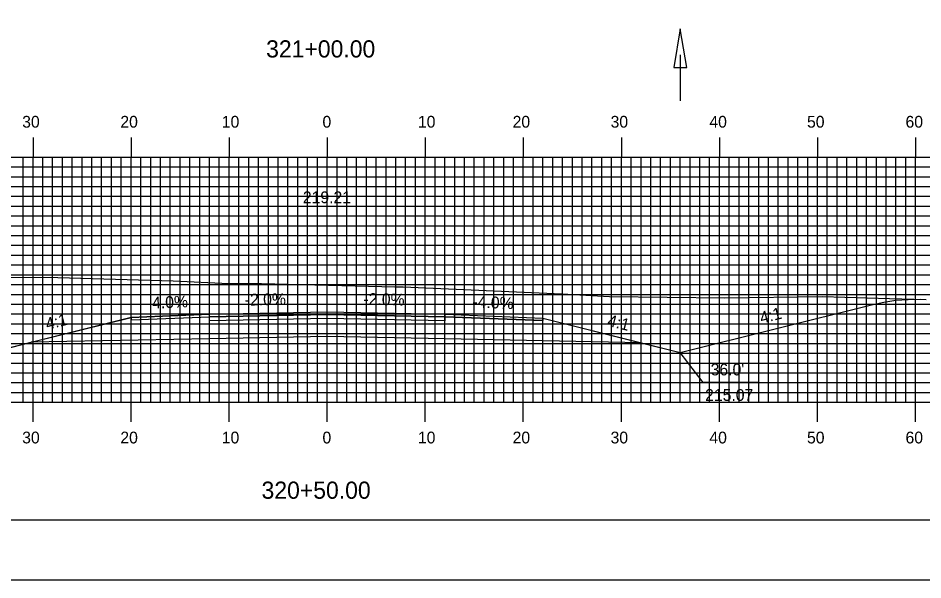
# Model space of a CAD drawing. Extents: x 1820424 to 1820768, y 442591 to 442811.
# Drawn here: x 1820558.7 to 1820650.9, y 442590.5 to 442647.8 of the extents above; entities that cross this region are included whole.
import ezdxf

# ---------------------------------------------------------------- set-up
doc = ezdxf.new("R2010")
doc.units = 0
for name, color, linetype in [('ANNOTATION', 7, 'Continuous'), ('BORDER', 7, 'Continuous'), ('D_Drainage_Ditch_Line', 7, 'Continuous'), ('D_Roadway_Centerline', 7, 'Continuous'), ('D_Roadway_Centerline_Text', 7, 'Continuous'), ('D_Roadway_Edge_Shoulder', 7, 'Continuous'), ('D_Roadway_Edge_TW', 7, 'Continuous'), ('D_Roadway_Pavement', 7, 'Continuous'), ('D_Roadway_SlopeLines', 7, 'Continuous'), ('D_Roadway_SubGrade', 7, 'Continuous'), ('H_V ANNOTATION', 7, 'Continuous'), ('MAJOR', 7, 'Continuous'), ('MINOR', 7, 'Continuous'), ('PLOT BOUNDARY', 7, 'Continuous'), ('S_Roadway_Centerline', 7, 'Continuous')]:
    doc.layers.add(name, color=color, linetype=linetype)

msp = doc.modelspace()

# ---------------------------------------------------------------- linework, layer by layer
at = {"layer": 'ANNOTATION'}
msp.add_lwpolyline([(1820634.22, 442610.677), (1820628.528, 442610.677), (1820626.204, 442613.737)], dxfattribs=at)
at = {"layer": 'BORDER'}
msp.add_lwpolyline([(1820440.604, 442596.665), (1820760.604, 442596.665), (1820760.604, 442806.665), (1820440.604, 442806.665)], close=True, dxfattribs=at)
at = {"layer": 'D_Drainage_Ditch_Line'}
msp.add_line((1820626.204, 442644.105), (1820626.204, 442639.406), dxfattribs=at)
msp.add_lwpolyline([(1820625.548, 442642.793), (1820626.86, 442642.793), (1820626.204, 442646.73)], close=True, dxfattribs=at)
at = {"layer": 'D_Roadway_Centerline'}
msp.add_lwpolyline([(1820520.686, 442622.127), (1820521.936, 442622.025), (1820523.186, 442621.863), (1820524.436, 442621.641), (1820525.686, 442621.359), (1820556.03, 442613.773), (1820560.03, 442614.773), (1820570.204, 442617.317), (1820578.204, 442617.637), (1820590.204, 442617.877), (1820602.204, 442617.637), (1820612.204, 442617.237), (1820622.204, 442614.737), (1820626.204, 442613.737), (1820645.702, 442618.611), (1820646.952, 442618.88), (1820648.202, 442619.061), (1820649.452, 442619.155), (1820650.702, 442619.161)], dxfattribs=at)
at = {"layer": 'D_Roadway_Edge_Shoulder'}
for points in [[(1820578.204, 442617.637), (1820570.204, 442617.317), (1820570.204, 442617.067), (1820578.204, 442617.387)], [(1820602.204, 442617.637), (1820612.204, 442617.237), (1820612.204, 442616.987), (1820602.204, 442617.387)]]:
    msp.add_lwpolyline(points, close=True, dxfattribs=at)
at = {"layer": 'D_Roadway_Edge_TW'}
msp.add_lwpolyline([(1820578.204, 442617.387), (1820578.204, 442617.637), (1820590.204, 442617.877), (1820602.204, 442617.637), (1820602.204, 442617.387), (1820590.204, 442617.627)], close=True, dxfattribs=at)
at = {"layer": 'D_Roadway_Pavement'}
msp.add_lwpolyline([(1820578.204, 442616.97), (1820578.204, 442617.387), (1820590.204, 442617.627), (1820602.204, 442617.387), (1820602.204, 442616.97), (1820590.204, 442617.21)], close=True, dxfattribs=at)
at = {"layer": 'D_Roadway_SlopeLines'}
for points in [[(1820626.204, 442613.737), (1820645.702, 442618.611), (1820646.952, 442618.88), (1820648.202, 442619.061), (1820649.452, 442619.155), (1820650.702, 442619.161)], [(1820570.204, 442617.317), (1820556.03, 442613.773)], [(1820612.204, 442617.237), (1820626.204, 442613.737)]]:
    msp.add_lwpolyline(points, dxfattribs=at)
at = {"layer": 'D_Roadway_SubGrade'}
msp.add_lwpolyline([(1820578.204, 442615.137), (1820560.03, 442614.773), (1820570.204, 442617.317), (1820570.204, 442617.067), (1820578.204, 442617.387), (1820590.204, 442617.627), (1820602.204, 442617.387), (1820612.204, 442616.987), (1820612.204, 442617.237), (1820622.204, 442614.737), (1820602.204, 442615.137), (1820590.204, 442615.377)], close=True, dxfattribs=at)
at = {"layer": 'MAJOR'}
for p, q in [((1820560.204, 442635.669), (1820560.204, 442633.665)), ((1820570.204, 442635.669), (1820570.204, 442633.665)), ((1820580.204, 442635.669), (1820580.204, 442633.665)), ((1820590.204, 442635.669), (1820590.204, 442633.665)), ((1820600.204, 442635.669), (1820600.204, 442633.665)), ((1820610.204, 442635.669), (1820610.204, 442633.665)), ((1820620.204, 442635.669), (1820620.204, 442633.665)), ((1820630.204, 442635.669), (1820630.204, 442633.665)), ((1820640.204, 442635.669), (1820640.204, 442633.665)), ((1820650.204, 442635.669), (1820650.204, 442633.665)), ((1820450.204, 442633.665), (1820730.204, 442633.665)), ((1820450.204, 442633.665), (1820730.204, 442633.665)), ((1820560.204, 442608.665), (1820560.204, 442633.665)), ((1820570.204, 442608.665), (1820570.204, 442633.665)), ((1820580.204, 442608.665), (1820580.204, 442633.665)), ((1820590.204, 442608.665), (1820590.204, 442633.665)), ((1820600.204, 442608.665), (1820600.204, 442633.665)), ((1820610.204, 442608.665), (1820610.204, 442633.665)), ((1820620.204, 442608.665), (1820620.204, 442633.665)), ((1820630.204, 442608.665), (1820630.204, 442633.665)), ((1820640.204, 442608.665), (1820640.204, 442633.665)), ((1820650.204, 442608.665), (1820650.204, 442633.665)), ((1820450.204, 442628.665), (1820730.204, 442628.665)), ((1820450.204, 442623.665), (1820730.204, 442623.665)), ((1820450.204, 442618.665), (1820730.204, 442618.665)), ((1820450.204, 442613.665), (1820730.204, 442613.665)), ((1820450.204, 442608.665), (1820730.204, 442608.665)), ((1820450.204, 442608.665), (1820730.204, 442608.665)), ((1820560.204, 442606.661), (1820560.204, 442608.665)), ((1820570.204, 442606.661), (1820570.204, 442608.665)), ((1820580.204, 442606.661), (1820580.204, 442608.665)), ((1820590.204, 442606.661), (1820590.204, 442608.665)), ((1820600.204, 442606.661), (1820600.204, 442608.665)), ((1820610.204, 442606.661), (1820610.204, 442608.665)), ((1820620.204, 442606.661), (1820620.204, 442608.665)), ((1820630.204, 442606.661), (1820630.204, 442608.665)), ((1820640.204, 442606.661), (1820640.204, 442608.665)), ((1820650.204, 442606.661), (1820650.204, 442608.665))]:
    msp.add_line(p, q, dxfattribs=at)
at = {"layer": 'MINOR'}
for p, q in [((1820559.204, 442608.665), (1820559.204, 442633.665)), ((1820561.204, 442608.665), (1820561.204, 442633.665)), ((1820562.204, 442608.665), (1820562.204, 442633.665)), ((1820563.204, 442608.665), (1820563.204, 442633.665)), ((1820564.204, 442608.665), (1820564.204, 442633.665)), ((1820565.204, 442608.665), (1820565.204, 442633.665)), ((1820566.204, 442608.665), (1820566.204, 442633.665)), ((1820567.204, 442608.665), (1820567.204, 442633.665)), ((1820568.204, 442608.665), (1820568.204, 442633.665)), ((1820569.204, 442608.665), (1820569.204, 442633.665)), ((1820571.204, 442608.665), (1820571.204, 442633.665)), ((1820572.204, 442608.665), (1820572.204, 442633.665)), ((1820573.204, 442608.665), (1820573.204, 442633.665)), ((1820574.204, 442608.665), (1820574.204, 442633.665)), ((1820575.204, 442608.665), (1820575.204, 442633.665)), ((1820576.204, 442608.665), (1820576.204, 442633.665)), ((1820577.204, 442608.665), (1820577.204, 442633.665)), ((1820578.204, 442608.665), (1820578.204, 442633.665)), ((1820579.204, 442608.665), (1820579.204, 442633.665)), ((1820581.204, 442608.665), (1820581.204, 442633.665)), ((1820582.204, 442608.665), (1820582.204, 442633.665)), ((1820583.204, 442608.665), (1820583.204, 442633.665)), ((1820584.204, 442608.665), (1820584.204, 442633.665)), ((1820585.204, 442608.665), (1820585.204, 442633.665)), ((1820586.204, 442608.665), (1820586.204, 442633.665)), ((1820587.204, 442608.665), (1820587.204, 442633.665)), ((1820588.204, 442608.665), (1820588.204, 442633.665)), ((1820589.204, 442608.665), (1820589.204, 442633.665)), ((1820591.204, 442608.665), (1820591.204, 442633.665)), ((1820592.204, 442608.665), (1820592.204, 442633.665)), ((1820593.204, 442608.665), (1820593.204, 442633.665)), ((1820594.204, 442608.665), (1820594.204, 442633.665)), ((1820595.204, 442608.665), (1820595.204, 442633.665)), ((1820596.204, 442608.665), (1820596.204, 442633.665)), ((1820597.204, 442608.665), (1820597.204, 442633.665)), ((1820598.204, 442608.665), (1820598.204, 442633.665)), ((1820599.204, 442608.665), (1820599.204, 442633.665)), ((1820601.204, 442608.665), (1820601.204, 442633.665)), ((1820602.204, 442608.665), (1820602.204, 442633.665)), ((1820603.204, 442608.665), (1820603.204, 442633.665)), ((1820604.204, 442608.665), (1820604.204, 442633.665)), ((1820605.204, 442608.665), (1820605.204, 442633.665)), ((1820606.204, 442608.665), (1820606.204, 442633.665)), ((1820607.204, 442608.665), (1820607.204, 442633.665)), ((1820608.204, 442608.665), (1820608.204, 442633.665)), ((1820609.204, 442608.665), (1820609.204, 442633.665)), ((1820611.204, 442608.665), (1820611.204, 442633.665)), ((1820612.204, 442608.665), (1820612.204, 442633.665)), ((1820613.204, 442608.665), (1820613.204, 442633.665)), ((1820614.204, 442608.665), (1820614.204, 442633.665)), ((1820615.204, 442608.665), (1820615.204, 442633.665)), ((1820616.204, 442608.665), (1820616.204, 442633.665)), ((1820617.204, 442608.665), (1820617.204, 442633.665)), ((1820618.204, 442608.665), (1820618.204, 442633.665)), ((1820619.204, 442608.665), (1820619.204, 442633.665)), ((1820621.204, 442608.665), (1820621.204, 442633.665)), ((1820622.204, 442608.665), (1820622.204, 442633.665)), ((1820623.204, 442608.665), (1820623.204, 442633.665)), ((1820624.204, 442608.665), (1820624.204, 442633.665)), ((1820625.204, 442608.665), (1820625.204, 442633.665)), ((1820626.204, 442608.665), (1820626.204, 442633.665)), ((1820627.204, 442608.665), (1820627.204, 442633.665)), ((1820628.204, 442608.665), (1820628.204, 442633.665)), ((1820629.204, 442608.665), (1820629.204, 442633.665)), ((1820631.204, 442608.665), (1820631.204, 442633.665)), ((1820632.204, 442608.665), (1820632.204, 442633.665)), ((1820633.204, 442608.665), (1820633.204, 442633.665)), ((1820634.204, 442608.665), (1820634.204, 442633.665)), ((1820635.204, 442608.665), (1820635.204, 442633.665)), ((1820636.204, 442608.665), (1820636.204, 442633.665)), ((1820637.204, 442608.665), (1820637.204, 442633.665)), ((1820638.204, 442608.665), (1820638.204, 442633.665)), ((1820639.204, 442608.665), (1820639.204, 442633.665)), ((1820641.204, 442608.665), (1820641.204, 442633.665)), ((1820642.204, 442608.665), (1820642.204, 442633.665)), ((1820643.204, 442608.665), (1820643.204, 442633.665)), ((1820644.204, 442608.665), (1820644.204, 442633.665)), ((1820645.204, 442608.665), (1820645.204, 442633.665)), ((1820646.204, 442608.665), (1820646.204, 442633.665)), ((1820647.204, 442608.665), (1820647.204, 442633.665)), ((1820648.204, 442608.665), (1820648.204, 442633.665)), ((1820649.204, 442608.665), (1820649.204, 442633.665)), ((1820450.204, 442632.665), (1820730.204, 442632.665)), ((1820450.204, 442631.665), (1820730.204, 442631.665)), ((1820450.204, 442630.665), (1820730.204, 442630.665)), ((1820450.204, 442629.665), (1820730.204, 442629.665)), ((1820450.204, 442627.665), (1820730.204, 442627.665)), ((1820450.204, 442626.665), (1820730.204, 442626.665)), ((1820450.204, 442625.665), (1820730.204, 442625.665)), ((1820450.204, 442624.665), (1820730.204, 442624.665)), ((1820450.204, 442622.665), (1820730.204, 442622.665)), ((1820450.204, 442621.665), (1820730.204, 442621.665)), ((1820450.204, 442620.665), (1820730.204, 442620.665)), ((1820450.204, 442619.665), (1820730.204, 442619.665)), ((1820450.204, 442617.665), (1820730.204, 442617.665)), ((1820450.204, 442616.665), (1820730.204, 442616.665)), ((1820450.204, 442615.665), (1820730.204, 442615.665)), ((1820450.204, 442614.665), (1820730.204, 442614.665)), ((1820450.204, 442612.665), (1820730.204, 442612.665)), ((1820450.204, 442611.665), (1820730.204, 442611.665)), ((1820450.204, 442610.665), (1820730.204, 442610.665)), ((1820450.204, 442609.665), (1820730.204, 442609.665))]:
    msp.add_line(p, q, dxfattribs=at)
at = {"layer": 'PLOT BOUNDARY'}
msp.add_lwpolyline([(1820424.417, 442590.547), (1820764.417, 442590.547), (1820764.417, 442810.547), (1820424.417, 442810.547)], close=True, dxfattribs=at)
at = {"layer": 'S_Roadway_Centerline'}
msp.add_lwpolyline([(1820497.558, 442623.447), (1820526.172, 442621.814), (1820528.294, 442621.722), (1820535.962, 442621.616), (1820544.011, 442621.585), (1820545.636, 442621.622), (1820546.858, 442621.5), (1820562.734, 442621.392), (1820574.512, 442621.054), (1820580.165, 442620.785), (1820583.512, 442620.757), (1820595.775, 442620.473), (1820597.095, 442620.445), (1820597.938, 442620.431), (1820614.122, 442619.717), (1820618.996, 442619.451), (1820630.753, 442619.307), (1820640.71, 442619.43), (1820647.54, 442619.256), (1820651.297, 442619.143)], dxfattribs=at)

# ---------------------------------------------------------------- texts
at = {"layer": 'ANNOTATION'}
for s, rotation, p in [('-2.0%', 1.14576, (1820581.81, 442618.509)), ('-2.0%', 358.85424, (1820593.89, 442618.603)), ('-4.0%', 2.29061, (1820571.836, 442618.184)), ('-4.0%', 357.70939, (1820604.996, 442618.327)), ('4:1', 14.03624, (1820634.489, 442616.669)), ('4:1', 14.03624, (1820561.652, 442616.04)), ('4:1', 345.96376, (1820618.71, 442616.472))]:
    msp.add_text(s, height=1.2, rotation=rotation, dxfattribs=at).set_placement(p)
for s, p in [("36.0'", (1820629.306, 442611.403)), ('215.07', (1820628.744, 442608.803))]:
    msp.add_text(s, height=1.2, dxfattribs=at).set_placement(p)
at = {"layer": 'D_Roadway_Centerline'}
for s, p in [('C', (1820590.199, 442617.877)), ('L', (1820590.204, 442617.869))]:
    msp.add_text(s, height=0.0146, dxfattribs=at).set_placement(p)
at = {"layer": 'D_Roadway_Centerline_Text'}
msp.add_text('219.21', height=1.2, dxfattribs=at).set_placement((1820587.721, 442628.962))
at = {"layer": 'H_V ANNOTATION'}
for s, height, p in [('321+00.00', 1.75, (1820583.977, 442643.821)), ('30', 1.2, (1820559.101, 442636.665)), ('20', 1.2, (1820569.112, 442636.665)), ('10', 1.2, (1820579.455, 442636.665)), ('0', 1.2, (1820589.722, 442636.665)), ('10', 1.2, (1820599.455, 442636.665)), ('20', 1.2, (1820609.112, 442636.665)), ('30', 1.2, (1820619.101, 442636.665)), ('40', 1.2, (1820629.176, 442636.665)), ('50', 1.2, (1820639.133, 442636.665)), ('60', 1.2, (1820649.176, 442636.665)), ('30', 1.2, (1820559.101, 442604.465)), ('20', 1.2, (1820569.112, 442604.465)), ('10', 1.2, (1820579.455, 442604.465)), ('0', 1.2, (1820589.722, 442604.465)), ('10', 1.2, (1820599.455, 442604.465)), ('20', 1.2, (1820609.112, 442604.465)), ('30', 1.2, (1820619.101, 442604.465)), ('40', 1.2, (1820629.176, 442604.465)), ('50', 1.2, (1820639.133, 442604.465)), ('60', 1.2, (1820649.176, 442604.465)), ('320+50.00', 1.75, (1820583.509, 442598.821))]:
    msp.add_text(s, height=height, dxfattribs=at).set_placement(p)

doc.saveas('drawing.dxf')
